(* Logix 5000 project; controller AMCI_3601_AOP_AOI_Sample_RSLogix_V28 vendor 1 type 14 code 108 rev 28.11; software revision 28.00 *)

TASK MainTask (continuous, watchdog 500 ms) : MainProgram

MODULES
   Local : vendor 1 type 14 code 108 (Compact 0, rev 28.11)
      AMCI_3601 : vendor 10 type 10 code 25 (Compact 1, rev 3.1, Output RPI 2 ms)
           Local:1:O.Data0   // 3601 output dataw
END_MODULES

ADD_ON_INSTRUCTION AMCI_3601_AOP_Absolute_Move   (* revision 0.0, vendor AMCI, ExecuteEnableInFalse *)
// Revision note:
// 3/2020: Version 0 is the initial release
VAR_INPUT
   Axis_Status_Bits : INT; {required}
   _0_normal_1_S_Curve_Acceleration : BOOL;
   _0_Triangular_1_Trapezoidal_S_Curve : BOOL;
   _0_Target_Move_1_Encoder_Move : BOOL;
   Target_Position : DINT; {required}
   Programmed_Speed : DINT; {required}
   Acceleration : INT; {required}
   Deceleration : INT; {required}
END_VAR
VAR_OUTPUT
   EN : BOOL; {access Read Only, visible}
   ER : BOOL; {access Read Only, visible}
END_VAR
VAR_IN_OUT
   AMCI_3601_output_data : AM:1769_3601:O:0; {required}
END_VAR
VAR
   Upper_Result_X_1000 : DINT;
   command_data_block : INT[10];
        [4]   // Upper Programmed Speed
        [0]   // Command Bits MSW
        [2]   // Upper Target Position
        [3]   // Lower Target Position
        [5]   // Lower Programmed Speed
        [1]   // Command Bits LSW
END_VAR

ROUTINE EnableInFalse   (* ladder *)
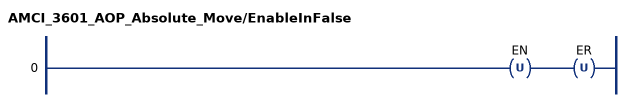
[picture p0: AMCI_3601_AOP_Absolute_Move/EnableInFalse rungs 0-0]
   0: OTU(EN)OTU(ER);
END_ROUTINE

ROUTINE Logic   (* ladder *)
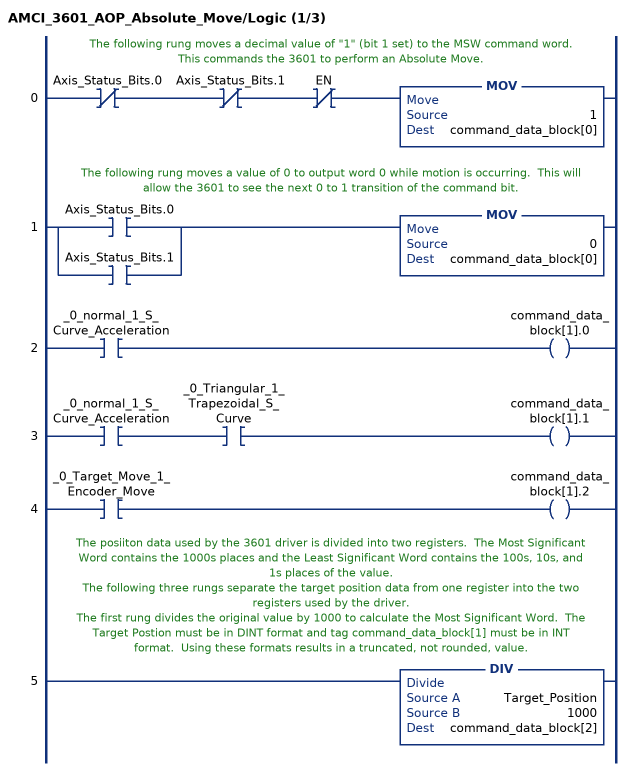
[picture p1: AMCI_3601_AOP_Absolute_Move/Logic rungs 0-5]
   // The following rung moves a decimal value of "1" (bit 1 set) to the MSW command word.  This commands the 3601 to perform an Absolute Move.
   0: XIO(Axis_Status_Bits.0)XIO(Axis_Status_Bits.1)XIO(EN)MOV(1,command_data_block[0]);
   // The following rung moves a value of 0 to output word 0 while motion is occurring.  This will allow the 3601 to see the next 0 to 1 transition of the command bit.
   1: [XIC(Axis_Status_Bits.0) ,XIC(Axis_Status_Bits.1) ]MOV(0,command_data_block[0]);
   2: XIC(_0_normal_1_S_Curve_Acceleration)OTE(command_data_block[1].0);
   3: XIC(_0_normal_1_S_Curve_Acceleration)XIC(_0_Triangular_1_Trapezoidal_S_Curve)OTE(command_data_block[1].1);
   4: XIC(_0_Target_Move_1_Encoder_Move)OTE(command_data_block[1].2);
   // The posiiton data used by the 3601 driver is divided into two registers.  The Most Significant Word contains the 1000s places and the Least Significant Word contains the 100s, 10s, and 1s places of the value.
   // The following three rungs separate the target position data from one register into the two registers used by the driver.
   // The first rung divides the original value by 1000 to calculate the Most Significant Word.  The Target Postion must be in DINT format and tag command_data_block[1] must be in INT format.  Using these formats results in a truncated, not rounded, value.
   5: DIV(Target_Position,1000,command_data_block[2]);
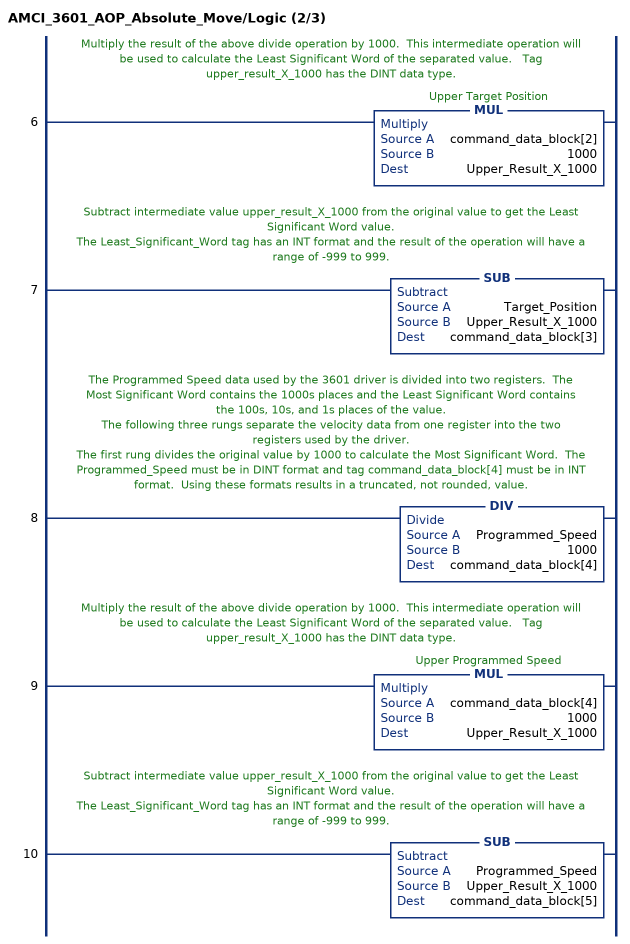
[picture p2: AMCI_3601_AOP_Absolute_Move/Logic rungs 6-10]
   // Multiply the result of the above divide operation by 1000.  This intermediate operation will be used to calculate the Least Significant Word of the separated value.   Tag upper_result_X_1000 has the DINT data type.
   6: MUL(command_data_block[2],1000,Upper_Result_X_1000);
   // Subtract intermediate value upper_result_X_1000 from the original value to get the Least Significant Word value.
   // The Least_Significant_Word tag has an INT format and the result of the operation will have a range of -999 to 999.
   7: SUB(Target_Position,Upper_Result_X_1000,command_data_block[3]);
   // The Programmed Speed data used by the 3601 driver is divided into two registers.  The Most Significant Word contains the 1000s places and the Least Significant Word contains the 100s, 10s, and 1s places of the value.
   // The following three rungs separate the velocity data from one register into the two registers used by the driver.
   // The first rung divides the original value by 1000 to calculate the Most Significant Word.  The Programmed_Speed must be in DINT format and tag command_data_block[4] must be in INT format.  Using these formats results in a truncated, not rounded, value.
   8: DIV(Programmed_Speed,1000,command_data_block[4]);
   // Multiply the result of the above divide operation by 1000.  This intermediate operation will be used to calculate the Least Significant Word of the separated value.   Tag upper_result_X_1000 has the DINT data type.
   9: MUL(command_data_block[4],1000,Upper_Result_X_1000);
   // Subtract intermediate value upper_result_X_1000 from the original value to get the Least Significant Word value.
   // The Least_Significant_Word tag has an INT format and the result of the operation will have a range of -999 to 999.
   10: SUB(Programmed_Speed,Upper_Result_X_1000,command_data_block[5]);
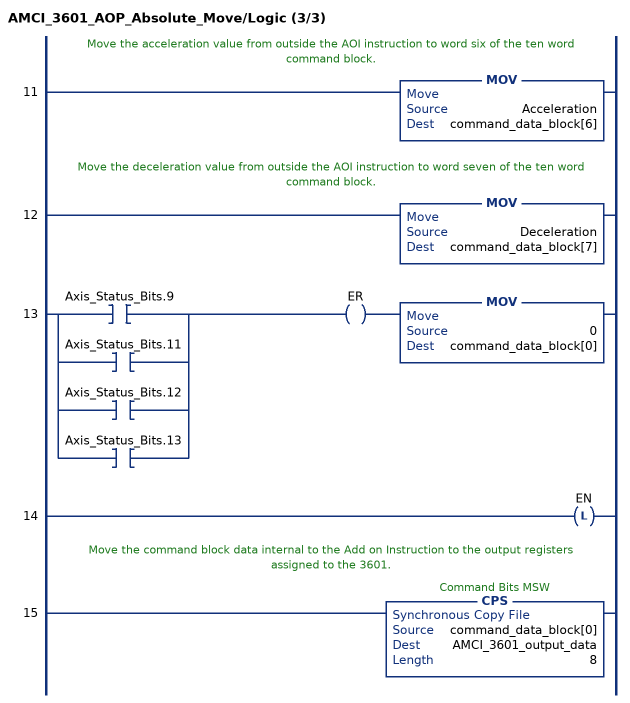
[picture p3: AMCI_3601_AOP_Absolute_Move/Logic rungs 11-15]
   // Move the acceleration value from outside the AOI instruction to word six of the ten word command block.
   11: MOV(Acceleration,command_data_block[6]);
   // Move the deceleration value from outside the AOI instruction to word seven of the ten word command block.
   12: MOV(Deceleration,command_data_block[7]);
   13: [XIC(Axis_Status_Bits.9) ,XIC(Axis_Status_Bits.11) ,XIC(Axis_Status_Bits.12) ,XIC(Axis_Status_Bits.13) ]OTE(ER)MOV(0,command_data_block[0]);
   14: OTL(EN);
   // Move the command block data internal to the Add on Instruction to the output registers assigned to the 3601.
   15: CPS(command_data_block[0],AMCI_3601_output_data,8);
END_ROUTINE
END_ADD_ON_INSTRUCTION

ADD_ON_INSTRUCTION AMCI_3601_AOP_Configure   (* revision 0.0 *)
// Revision note:
// 3/2020: Version 0 is the initial release
// Help:
// The Limit Input can only be configured to have one function, ESTOP, CW Limit, or CCW Limit.  The 3401_Configure_AOI will disable the Limit Input if more than one type of functionality is selected.
VAR_INPUT
   Capture_Input : BOOL; {required}
   Capture_Input_Active_State : BOOL; {required}
   External_Input : BOOL; {required}
   External_Input_Active_State : BOOL; {required}
   Home_Input : BOOL; {required}
   Home_Input_Active_State : BOOL; {required}
   Emergency_Stop_Input : BOOL; {required}
   Emerency_Stop_Active_State : BOOL; {required}
   CW_Limit : BOOL; {required}
   CW_Limit_Active_State : BOOL; {required}
   CCW_Limit : BOOL; {required}
   CCW_Limit_Active_State : BOOL; {required}
   Backplane_Home_Proximity_Enable : BOOL;
   Quadrature_Encoder : BOOL; {required}
   Diagnostic_Feedback : BOOL;
   _0_for_CW_CCW_1_for_step_direction : BOOL; {required}
   _0_Home_Limit_1_Marker_Pulse_Home : BOOL;
   starting_speed : DINT; {required}
END_VAR
VAR_IN_OUT
   AMCI_3601_output_data : AM:1769_3601:O:0; {required}
END_VAR
VAR
   upper_result_X_1000 : DINT;
   command_data_block : INT[8];
        [0].15   // Mode Bit 1=Configuraiton Mode 0=Command Mode
END_VAR

ROUTINE Logic   (* ladder *)
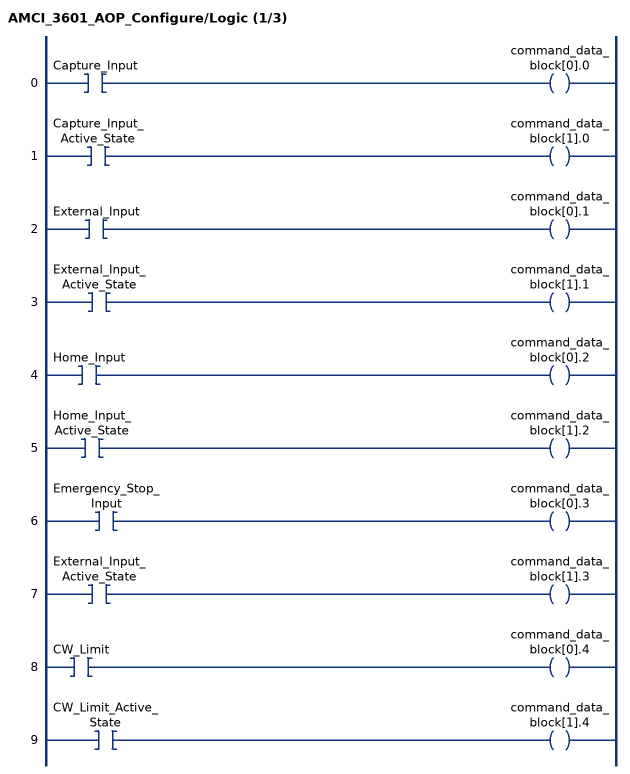
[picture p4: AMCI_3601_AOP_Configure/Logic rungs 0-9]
   0: XIC(Capture_Input)OTE(command_data_block[0].0);
   1: XIC(Capture_Input_Active_State)OTE(command_data_block[1].0);
   2: XIC(External_Input)OTE(command_data_block[0].1);
   3: XIC(External_Input_Active_State)OTE(command_data_block[1].1);
   4: XIC(Home_Input)OTE(command_data_block[0].2);
   5: XIC(Home_Input_Active_State)OTE(command_data_block[1].2);
   6: XIC(Emergency_Stop_Input)OTE(command_data_block[0].3);
   7: XIC(External_Input_Active_State)OTE(command_data_block[1].3);
   8: XIC(CW_Limit)OTE(command_data_block[0].4);
   9: XIC(CW_Limit_Active_State)OTE(command_data_block[1].4);
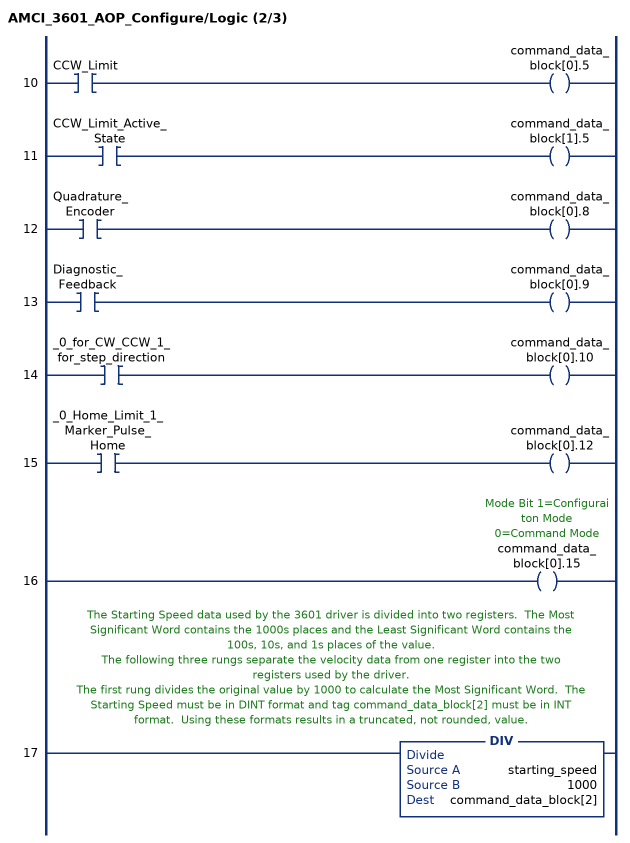
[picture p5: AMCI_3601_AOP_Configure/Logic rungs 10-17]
   10: XIC(CCW_Limit)OTE(command_data_block[0].5);
   11: XIC(CCW_Limit_Active_State)OTE(command_data_block[1].5);
   12: XIC(Quadrature_Encoder)OTE(command_data_block[0].8);
   13: XIC(Diagnostic_Feedback)OTE(command_data_block[0].9);
   14: XIC(_0_for_CW_CCW_1_for_step_direction)OTE(command_data_block[0].10);
   15: XIC(_0_Home_Limit_1_Marker_Pulse_Home)OTE(command_data_block[0].12);
   16: OTE(command_data_block[0].15);
   // The Starting Speed data used by the 3601 driver is divided into two registers.  The Most Significant Word contains the 1000s places and the Least Significant Word contains the 100s, 10s, and 1s places of the value.
   // The following three rungs separate the velocity data from one register into the two registers used by the driver.
   // The first rung divides the original value by 1000 to calculate the Most Significant Word.  The Starting Speed must be in DINT format and tag command_data_block[2] must be in INT format.  Using these formats results in a truncated, not rounded, value.
   17: DIV(starting_speed,1000,command_data_block[2]);
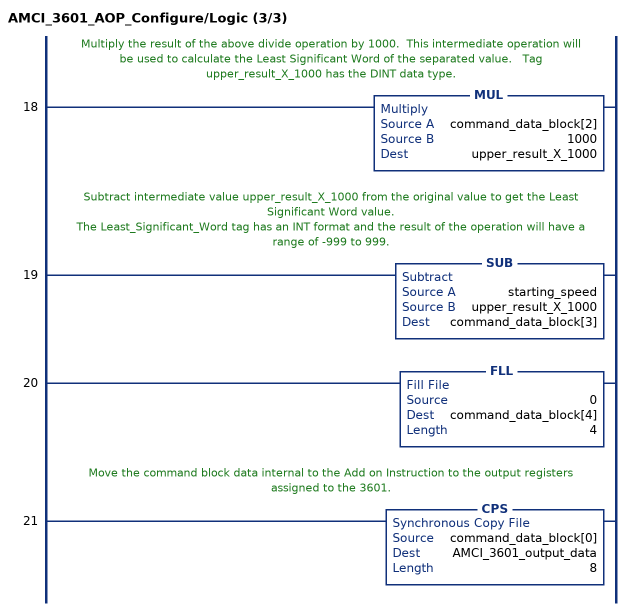
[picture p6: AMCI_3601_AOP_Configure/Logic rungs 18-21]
   // Multiply the result of the above divide operation by 1000.  This intermediate operation will be used to calculate the Least Significant Word of the separated value.   Tag upper_result_X_1000 has the DINT data type.
   18: MUL(command_data_block[2],1000,upper_result_X_1000);
   // Subtract intermediate value upper_result_X_1000 from the original value to get the Least Significant Word value.
   // The Least_Significant_Word tag has an INT format and the result of the operation will have a range of -999 to 999.
   19: SUB(starting_speed,upper_result_X_1000,command_data_block[3]);
   20: FLL(0,command_data_block[4],4);
   // Move the command block data internal to the Add on Instruction to the output registers assigned to the 3601.
   21: CPS(command_data_block[0],AMCI_3601_output_data,8);
END_ROUTINE
END_ADD_ON_INSTRUCTION

ADD_ON_INSTRUCTION AMCI_3601_AOP_Encoder_Follower   (* revision 0.0, vendor AMCI, ExecuteEnableInFalse *)
// Revision note:
// 3/2020: Version 0 is the initial release
VAR_INPUT
   Axis_Status_Bits : INT; {required}
   _0_same_1_opposite_direction : BOOL;
   _0_normal_1_S_Curve_Acceleration : BOOL;
   _0_Triangular_1_Trapezoidal_S_Curve : BOOL;
   Multiplier : INT; {required}
   Divisor : INT; {required}
   Acceleration : INT; {required}
   Deceleration : INT; {required}
END_VAR
VAR_OUTPUT
   EN : BOOL; {access Read Only, visible}
   Encoder_Follower_Occurring : BOOL; {access Read Only, visible}
   ER : BOOL; {access Read Only, visible}
END_VAR
VAR_IN_OUT
   AMCI_3601_output_data : AM:1769_3601:O:0; {required}
END_VAR
VAR
   Upper_Result_X_1000 : DINT;
   command_data_block : INT[10];
        [1]   // Command Bits LSW
        [3]   // Lower Target Position
        [5]   // Lower Programmed Speed
        [0]   // Command Bits MSW
        [2]   // Upper Target Position
        [4]   // Upper Programmed Speed
END_VAR

ROUTINE EnableInFalse   (* ladder *)
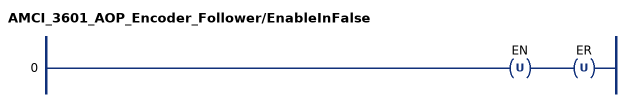
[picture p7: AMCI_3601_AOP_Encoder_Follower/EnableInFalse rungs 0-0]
   0: OTU(EN)OTU(ER);
END_ROUTINE

ROUTINE Logic   (* ladder *)
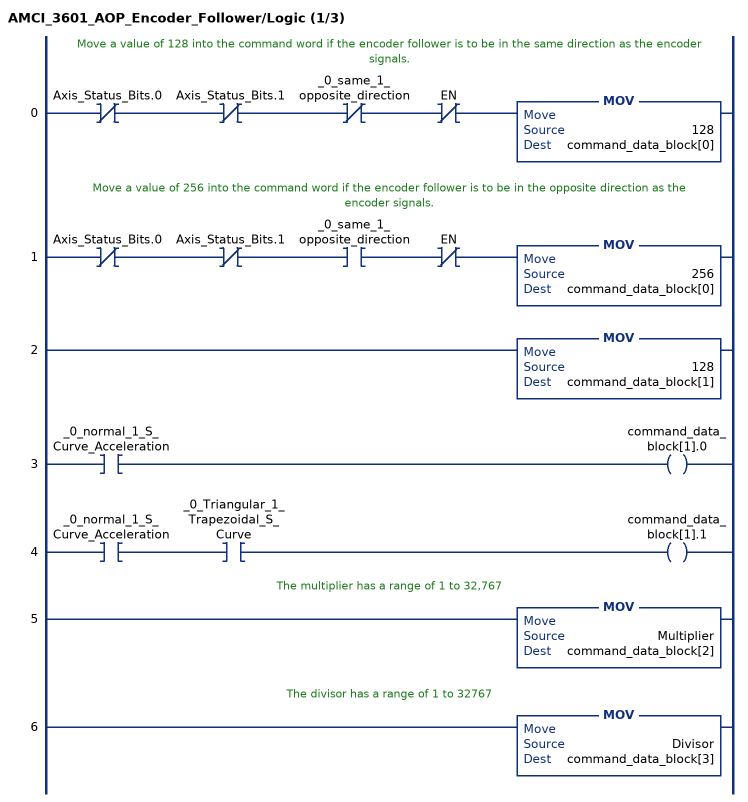
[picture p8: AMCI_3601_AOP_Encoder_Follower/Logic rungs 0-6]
   // Move a value of 128 into the command word if the encoder follower is to be in the same direction as the encoder signals.
   0: XIO(Axis_Status_Bits.0)XIO(Axis_Status_Bits.1)XIO(_0_same_1_opposite_direction)XIO(EN)MOV(128,command_data_block[0]);
   // Move a value of 256 into the command word if the encoder follower is to be in the opposite direction as the encoder signals.
   1: XIO(Axis_Status_Bits.0)XIO(Axis_Status_Bits.1)XIC(_0_same_1_opposite_direction)XIO(EN)MOV(256,command_data_block[0]);
   2: MOV(128,command_data_block[1]);
   3: XIC(_0_normal_1_S_Curve_Acceleration)OTE(command_data_block[1].0);
   4: XIC(_0_normal_1_S_Curve_Acceleration)XIC(_0_Triangular_1_Trapezoidal_S_Curve)OTE(command_data_block[1].1);
   // The multiplier has a range of 1 to 32,767
   5: MOV(Multiplier,command_data_block[2]);
   // The divisor has a range of 1 to 32767
   6: MOV(Divisor,command_data_block[3]);
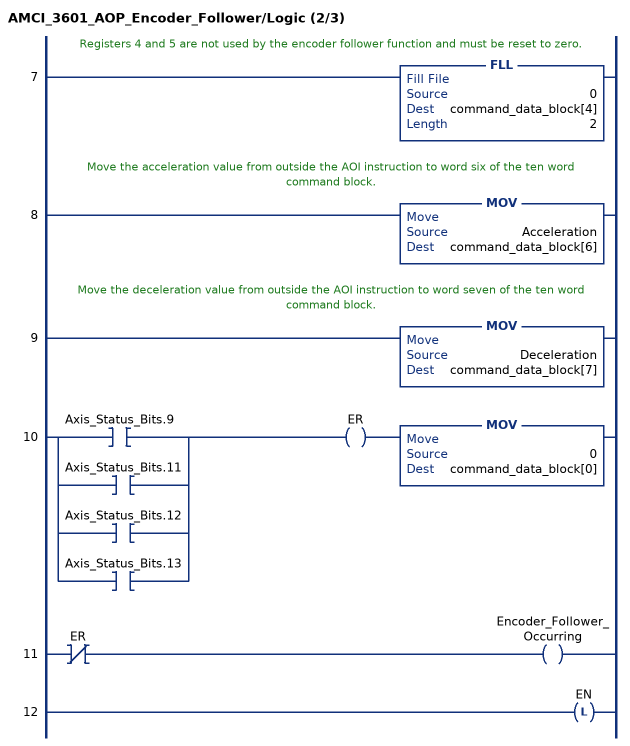
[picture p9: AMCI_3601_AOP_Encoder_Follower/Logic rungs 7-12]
   // Registers 4 and 5 are not used by the encoder follower function and must be reset to zero.
   7: FLL(0,command_data_block[4],2);
   // Move the acceleration value from outside the AOI instruction to word six of the ten word command block.
   8: MOV(Acceleration,command_data_block[6]);
   // Move the deceleration value from outside the AOI instruction to word seven of the ten word command block.
   9: MOV(Deceleration,command_data_block[7]);
   10: [XIC(Axis_Status_Bits.9) ,XIC(Axis_Status_Bits.11) ,XIC(Axis_Status_Bits.12) ,XIC(Axis_Status_Bits.13) ]OTE(ER)MOV(0,command_data_block[0]);
   11: XIO(ER)OTE(Encoder_Follower_Occurring);
   12: OTL(EN);
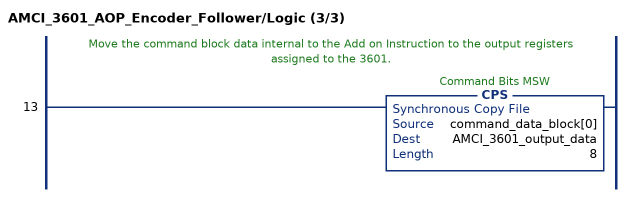
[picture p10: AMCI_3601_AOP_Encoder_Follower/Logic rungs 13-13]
   // Move the command block data internal to the Add on Instruction to the output registers assigned to the 3601.
   13: CPS(command_data_block[0],AMCI_3601_output_data,8);
END_ROUTINE
END_ADD_ON_INSTRUCTION

ADD_ON_INSTRUCTION AMCI_3601_AOP_Hold   (* revision 0.0, vendor AMCI, ExecuteEnableInFalse *)
// Revision note:
// 3/2020: Version 0 is the initial release
VAR_INPUT
   Axis_Status_Bits : INT; {required}
END_VAR
VAR_OUTPUT
   EN : BOOL; {access Read Only, visible}
   ER : BOOL; {access Read Only, visible}
END_VAR
VAR_IN_OUT
   AMCI_3601_output_data : AM:1769_3601:O:0; {required}
END_VAR
VAR
   Upper_Result_X_1000 : DINT;
   command_data_block : INT[10];
        [1]   // Command Bits LSW
        [3]   // Lower Target Position
        [5]   // Lower Programmed Speed
        [0]   // Command Bits MSW
        [2]   // Upper Target Position
        [4]   // Upper Programmed Speed
END_VAR

ROUTINE EnableInFalse   (* ladder *)
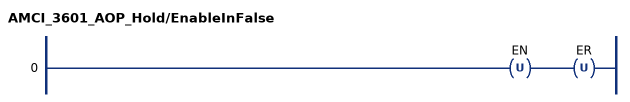
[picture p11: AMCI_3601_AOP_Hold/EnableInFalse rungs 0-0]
   0: OTU(EN)OTU(ER);
END_ROUTINE

ROUTINE Logic   (* ladder *)
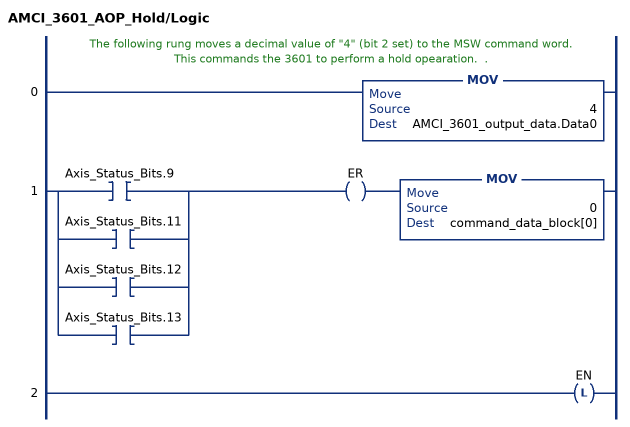
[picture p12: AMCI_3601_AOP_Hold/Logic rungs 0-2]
   // The following rung moves a decimal value of "4" (bit 2 set) to the MSW command word.  This commands the 3601 to perform a hold opearation.  .
   0: MOV(4,AMCI_3601_output_data.Data0);
   1: [XIC(Axis_Status_Bits.9) ,XIC(Axis_Status_Bits.11) ,XIC(Axis_Status_Bits.12) ,XIC(Axis_Status_Bits.13) ]OTE(ER)MOV(0,command_data_block[0]);
   2: OTL(EN);
END_ROUTINE
END_ADD_ON_INSTRUCTION

ADD_ON_INSTRUCTION AMCI_3601_AOP_Home_CCW   (* revision 0.0, vendor AMCI, ExecuteEnableInFalse *)
// Revision note:
// 3/2020: Version 0 is the initial release
VAR_INPUT
   Axis_Status_Bits : INT; {required}
   Programmed_Speed : DINT; {required}
   Acceleration : INT; {required}
   Deceleration : INT; {required}
END_VAR
VAR_OUTPUT
   EN : BOOL; {access Read Only, visible}
   ER : BOOL; {access Read Only, visible}
END_VAR
VAR_IN_OUT
   AMCI_3601_output_data : AM:1769_3601:O:0; {required}
END_VAR
VAR
   Upper_Result_X_1000 : DINT;
   command_data_block : INT[10];
        [1]   // Command Bits LSW
        [3]   // Lower Target Position
        [5]   // Lower Programmed Speed
        [0]   // Command Bits MSW
        [2]   // Upper Target Position
        [4]   // Upper Programmed Speed
END_VAR

ROUTINE EnableInFalse   (* ladder *)
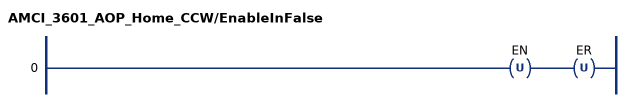
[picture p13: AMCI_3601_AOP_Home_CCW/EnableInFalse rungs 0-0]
   0: OTU(EN)OTU(ER);
END_ROUTINE

ROUTINE Logic   (* ladder *)
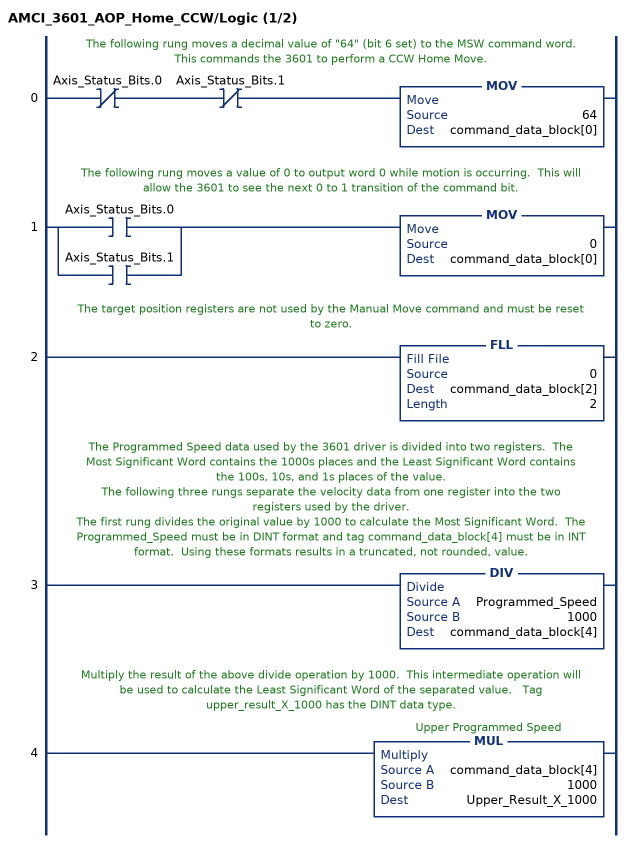
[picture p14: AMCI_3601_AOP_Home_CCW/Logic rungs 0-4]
   // The following rung moves a decimal value of "64" (bit 6 set) to the MSW command word.  This commands the 3601 to perform a CCW Home Move.
   0: XIO(Axis_Status_Bits.0)XIO(Axis_Status_Bits.1)MOV(64,command_data_block[0]);
   // The following rung moves a value of 0 to output word 0 while motion is occurring.  This will allow the 3601 to see the next 0 to 1 transition of the command bit.
   1: [XIC(Axis_Status_Bits.0) ,XIC(Axis_Status_Bits.1) ]MOV(0,command_data_block[0]);
   // The target position registers are not used by the Manual Move command and must be reset to zero.
   2: FLL(0,command_data_block[2],2);
   // The Programmed Speed data used by the 3601 driver is divided into two registers.  The Most Significant Word contains the 1000s places and the Least Significant Word contains the 100s, 10s, and 1s places of the value.
   // The following three rungs separate the velocity data from one register into the two registers used by the driver.
   // The first rung divides the original value by 1000 to calculate the Most Significant Word.  The Programmed_Speed must be in DINT format and tag command_data_block[4] must be in INT format.  Using these formats results in a truncated, not rounded, value.
   3: DIV(Programmed_Speed,1000,command_data_block[4]);
   // Multiply the result of the above divide operation by 1000.  This intermediate operation will be used to calculate the Least Significant Word of the separated value.   Tag upper_result_X_1000 has the DINT data type.
   4: MUL(command_data_block[4],1000,Upper_Result_X_1000);
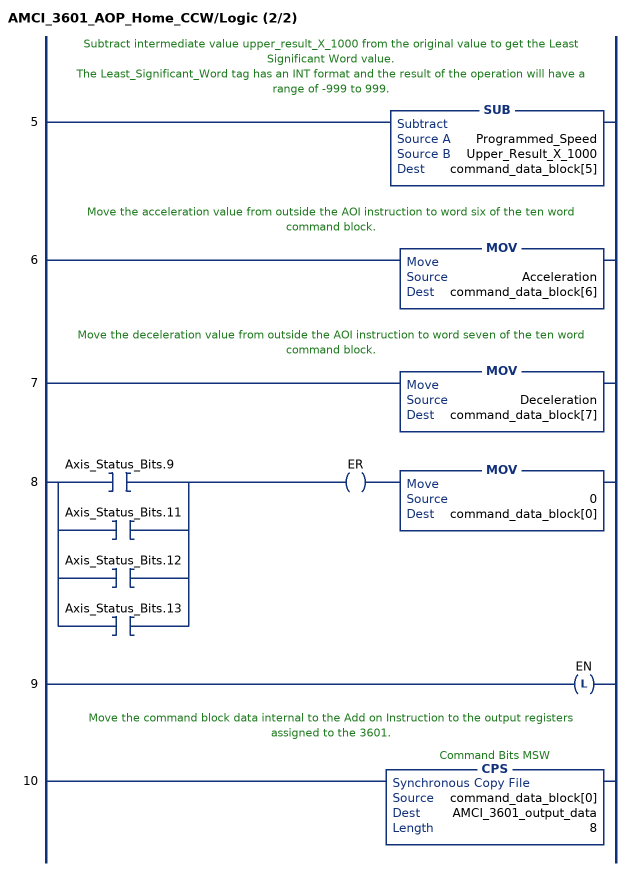
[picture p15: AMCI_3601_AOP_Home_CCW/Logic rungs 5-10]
   // Subtract intermediate value upper_result_X_1000 from the original value to get the Least Significant Word value.
   // The Least_Significant_Word tag has an INT format and the result of the operation will have a range of -999 to 999.
   5: SUB(Programmed_Speed,Upper_Result_X_1000,command_data_block[5]);
   // Move the acceleration value from outside the AOI instruction to word six of the ten word command block.
   6: MOV(Acceleration,command_data_block[6]);
   // Move the deceleration value from outside the AOI instruction to word seven of the ten word command block.
   7: MOV(Deceleration,command_data_block[7]);
   8: [XIC(Axis_Status_Bits.9) ,XIC(Axis_Status_Bits.11) ,XIC(Axis_Status_Bits.12) ,XIC(Axis_Status_Bits.13) ]OTE(ER)MOV(0,command_data_block[0]);
   9: OTL(EN);
   // Move the command block data internal to the Add on Instruction to the output registers assigned to the 3601.
   10: CPS(command_data_block[0],AMCI_3601_output_data,8);
END_ROUTINE
END_ADD_ON_INSTRUCTION

ADD_ON_INSTRUCTION AMCI_3601_AOP_Home_CW   (* revision 0.0, vendor AMCI, ExecuteEnableInFalse *)
// Revision note:
// 3/2020: Version 0 is the initial release
VAR_INPUT
   Axis_Status_Bits : INT; {required}
   Programmed_Speed : DINT; {required}
   Acceleration : INT; {required}
   Deceleration : INT; {required}
END_VAR
VAR_OUTPUT
   EN : BOOL; {access Read Only, visible}
   ER : BOOL; {access Read Only, visible}
END_VAR
VAR_IN_OUT
   AMCI_3601_output_data : AM:1769_3601:O:0; {required}
END_VAR
VAR
   Upper_Result_X_1000 : DINT;
   command_data_block : INT[10];
        [1]   // Command Bits LSW
        [3]   // Lower Target Position
        [5]   // Lower Programmed Speed
        [0]   // Command Bits MSW
        [2]   // Upper Target Position
        [4]   // Upper Programmed Speed
END_VAR

ROUTINE EnableInFalse   (* ladder *)
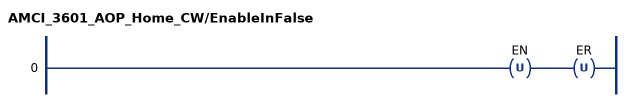
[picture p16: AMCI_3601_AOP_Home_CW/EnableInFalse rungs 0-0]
   0: OTU(EN)OTU(ER);
END_ROUTINE

ROUTINE Logic   (* ladder *)
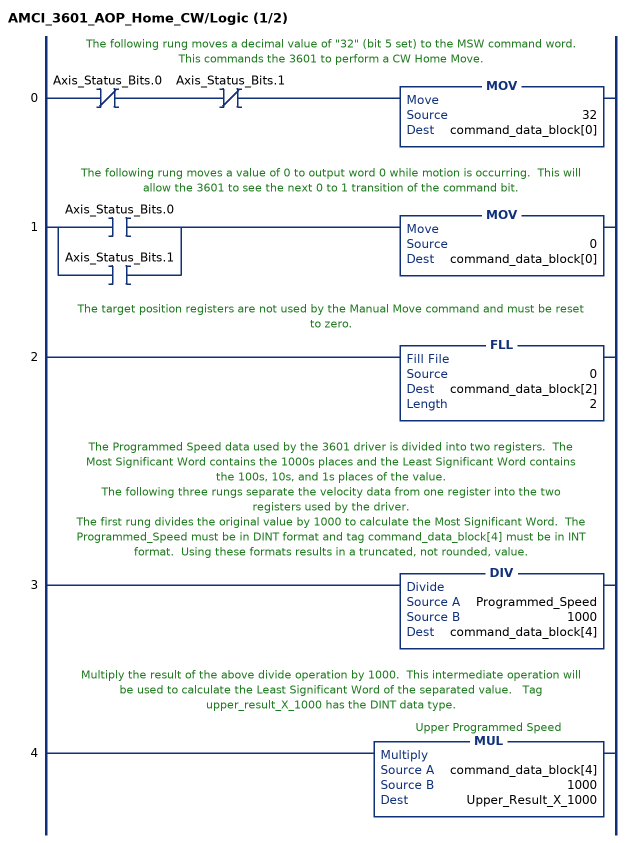
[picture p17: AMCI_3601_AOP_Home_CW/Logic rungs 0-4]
   // The following rung moves a decimal value of "32" (bit 5 set) to the MSW command word.  This commands the 3601 to perform a CW Home Move.
   0: XIO(Axis_Status_Bits.0)XIO(Axis_Status_Bits.1)MOV(32,command_data_block[0]);
   // The following rung moves a value of 0 to output word 0 while motion is occurring.  This will allow the 3601 to see the next 0 to 1 transition of the command bit.
   1: [XIC(Axis_Status_Bits.0) ,XIC(Axis_Status_Bits.1) ]MOV(0,command_data_block[0]);
   // The target position registers are not used by the Manual Move command and must be reset to zero.
   2: FLL(0,command_data_block[2],2);
   // The Programmed Speed data used by the 3601 driver is divided into two registers.  The Most Significant Word contains the 1000s places and the Least Significant Word contains the 100s, 10s, and 1s places of the value.
   // The following three rungs separate the velocity data from one register into the two registers used by the driver.
   // The first rung divides the original value by 1000 to calculate the Most Significant Word.  The Programmed_Speed must be in DINT format and tag command_data_block[4] must be in INT format.  Using these formats results in a truncated, not rounded, value.
   3: DIV(Programmed_Speed,1000,command_data_block[4]);
   // Multiply the result of the above divide operation by 1000.  This intermediate operation will be used to calculate the Least Significant Word of the separated value.   Tag upper_result_X_1000 has the DINT data type.
   4: MUL(command_data_block[4],1000,Upper_Result_X_1000);
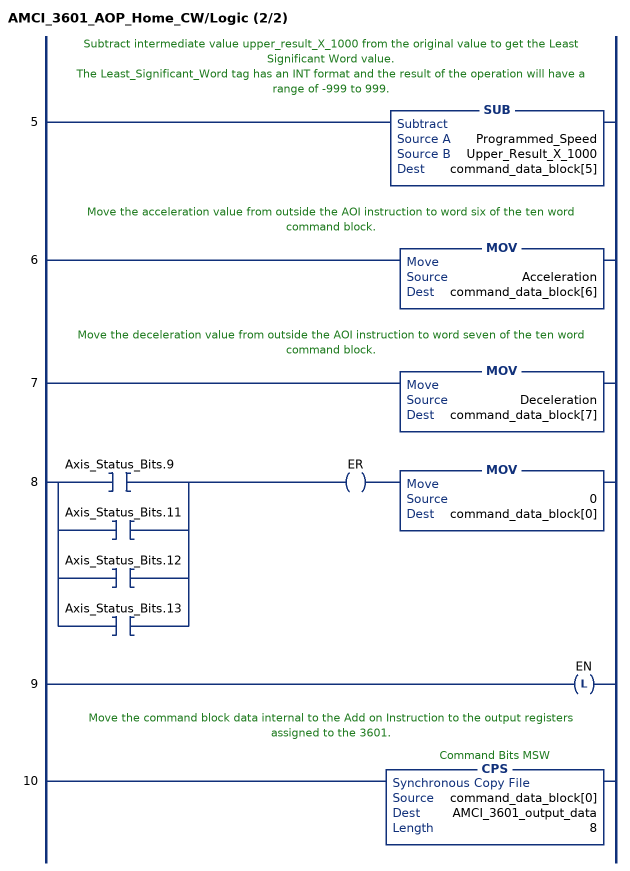
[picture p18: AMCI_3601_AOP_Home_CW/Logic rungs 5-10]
   // Subtract intermediate value upper_result_X_1000 from the original value to get the Least Significant Word value.
   // The Least_Significant_Word tag has an INT format and the result of the operation will have a range of -999 to 999.
   5: SUB(Programmed_Speed,Upper_Result_X_1000,command_data_block[5]);
   // Move the acceleration value from outside the AOI instruction to word six of the ten word command block.
   6: MOV(Acceleration,command_data_block[6]);
   // Move the deceleration value from outside the AOI instruction to word seven of the ten word command block.
   7: MOV(Deceleration,command_data_block[7]);
   8: [XIC(Axis_Status_Bits.9) ,XIC(Axis_Status_Bits.11) ,XIC(Axis_Status_Bits.12) ,XIC(Axis_Status_Bits.13) ]OTE(ER)MOV(0,command_data_block[0]);
   9: OTL(EN);
   // Move the command block data internal to the Add on Instruction to the output registers assigned to the 3601.
   10: CPS(command_data_block[0],AMCI_3601_output_data,8);
END_ROUTINE
END_ADD_ON_INSTRUCTION
